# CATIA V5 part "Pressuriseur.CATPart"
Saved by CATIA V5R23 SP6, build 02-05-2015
Part number: Pressuriseur
Publications: "CATRouFace1", "CATRouCenter1", "CATRouCircular1", "CATRouDatumPt1"
Bounding box of the stored display mesh (mm): x -1099.934 to 1577.794, y -1466.41 to 1466.41, z 0 to 12000
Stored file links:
  \\etu.ad.univ-lorraine.fr\bordron1\Documents\Parts EPR\Pressuriseur.CATPart
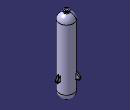
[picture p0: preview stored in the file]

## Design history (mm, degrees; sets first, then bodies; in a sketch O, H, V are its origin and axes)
AxisSystem1: origin (0, 0, 0), X (1, 0, 0), Y (0, 1, 0), Z (0, 0, 1)
Set1
  Point1: type Center, Curve edge [face of Shaft1 from Sketch1.L10 | face of Shaft1 from Sketch1.L9]
  Plane1: type Offset, RefPlane YZ plane of AxisSystem1, Offset 0
Body1 (main body)
  Sketch1 on YZ plane of AxisSystem1, origin (0, 0, 0), H (0, 1, 0), V (0, 0, 1)
    line L1 (-1100, 10683.5771) -> (-1100, 1270)
    reference projected line E1 through (0, 0) direction (0, 1) from edge [ZX plane of AxisSystem1 | YZ plane of AxisSystem1]
    arc A1 centre (0, 10683.5771) radius 1100 from (-403.3333, 11706.9648) to (-1100, 10683.5771) ccw
    point P3 (0, 10683.5771)
    arc A2 centre (0, 1270) radius 1100 from (-1100, 1270) to (-160, 181.6986) ccw
    point P4 (0, 1270)
    line L2 (-340, 11800) -> (-340, 11880)
    line L3 (-340, 11880) -> (-400, 11880)
    line L4 (-400, 11880) -> (-400, 12000)
    line L5 (-400, 12000) -> (-240, 12000)
    line L6 (-240, 12000) -> (-240, 11500)
    line L7 (-240, 11500) -> (0, 11500)
    point P11 (0, 11500)
    line L8 (-160, 181.6986) -> (-160, 0)
    line L9 (-160, 0) -> (-128, 0)
    line L10 (-128, 0) -> (-128, 500)
    line L11 (-128, 500) -> (0, 500)
    point P15 (0, 500)
    reference intersected line E2 through (0, 0) direction (0, 1) from ZX plane of AxisSystem1
    reference intersected line E3 through (0, 0) direction (0, 1) from ZX plane of AxisSystem1
    reference intersected line E4 through (0, 0) direction (0, 1) from ZX plane of AxisSystem1
    arc A3 centre (-440, 11800) radius 100 from (-403.3333, 11706.9648) to (-340, 11800) ccw
    distance L1 E1 = 1100
    distance L10 E2 = 128
    distance L8 E3 = 160
    distance L7 L11 = 11000
    distance L11 H = 500
    distance H P4 = 1270
    length L5 = 160
    length L4 = 120
    distance L2 L6 = 100
    distance L6 E4 = 240
    length L6 = 500
    radius A3 = 100
    length L2 = 80
    vertical: L1 V, L2 V, L4 V, L6 V, L8 V, L10 V
    coincidence: P3 V, P4 V, P11 V, P15 V, L9 H
    tangency: A1 L1, A2 L1, A3 L2, A3 A1
    horizontal: L3 H, L5 H, L7 H, L9 H, L11 H
  Shaft1: profile Sketch1, axis edge [ZX plane of AxisSystem1 | YZ plane of AxisSystem1], angle 360
  Sketch2 on XY plane of AxisSystem1, origin (0, 0, 0), H (1, 0, 0), V (0, 1, 0)
    projected circle E1 centre (0, 0) radius 1100 from face of Shaft1 from Sketch1.L1
    projected arc E2 centre (0, 0) radius 1100 from (1081.6654, -200) to (1081.6654, 200) ccw from face of Shaft1 from Sketch1.L1
    line L1 (1081.6654, 200) -> (1577.7944, 200)
    point P1 (1081.6654, 200)
    line L2 (1577.7944, 200) -> (1577.7944, -200)
    line L3 (1577.7944, -200) -> (1081.6654, -200)
    point P4 (1081.6654, -200)
    circle A1 centre (1411.2919, 0) radius 80
    point P5 (1411.2919, 0)
    radius A1 = 80
    length L2 = 400
    coincidence: P1 E1, P4 E1, P5 H
    horizontal: L1 H, L3 H
    vertical: L2 V
    symmetry: L3 L1 H
  Pad1: profile Sketch2, direction (0, 0, 1), length 3000, opposite side length -2920
  Sketch3 on face of Pad1 from Sketch2.L1, origin (0, 200, 0), H (-1, 0, 0), V (0, 0, 1)
    projected line E1 (-1577.7944, 3000) -> (-1081.6654, 3000) from edge [face of Pad1 from Sketch2.L1 | end face of Pad1]
    line L1 (-1577.7944, 3000) -> (-1577.7944, 3084.2813)
    line L2 (-1548.1938, 3182.5613) -> (-1200.6081, 3707.2453)
    arc A1 centre (-1399.8391, 3084.2813) radius 177.9553 from (-1577.7944, 3084.2813) to (-1548.1938, 3182.5613) cw
    line L3 (-1142.5429, 3738.4297) -> (-1023.8343, 3738.4297)
    line L4 (-1023.8343, 3738.4297) -> (-1081.6654, 3000)
    arc A2 centre (-1142.5429, 3668.779) radius 69.6507 from (-1200.6081, 3707.2453) to (-1142.5429, 3738.4297) cw
    radius A1 = 177.9553
    radius A2 = 69.6507
    vertical: L1 V
    tangency: A1 L1, A1 L2, A2 L2, A2 L3
    horizontal: L3 H
  Pad2: profile Sketch3, direction (0, -1, 0), length 60, opposite side length -20
  Pad3: profile Sketch3, direction (0, -1, 0), length 380, opposite side length -340
  CircPattern1: of Pad1, Sketch2, Pad2, Sketch3, Pad3, Sketch3, instances 3, angular step 120, axis from edge [ZX plane of AxisSystem1 | YZ plane of AxisSystem1]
